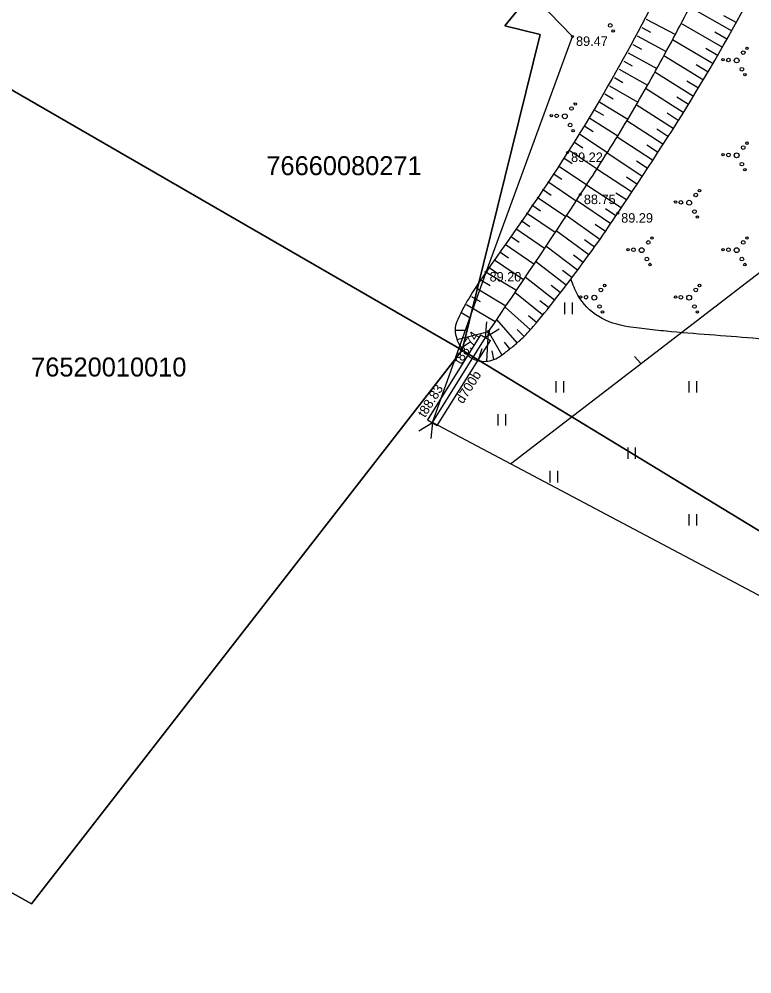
# Model space of a CAD drawing. Extents: x 635228 to 635525, y 248590 to 248800.
# Drawn here: x 635302.2 to 635340.8, y 248626.9 to 248677.2 of the extents above; entities that cross this region are included whole.
import ezdxf

# ---------------------------------------------------------------- set-up
doc = ezdxf.new("R2010")
doc.units = 0
for name, color, linetype in [('HIDT_CAUR_####_####_#', 7, 'Continuous'), ('HIDT_CAUR_####_TKST_#', 7, 'Continuous'), ('HIDT_CAUR_KONT_####_#', 7, 'Continuous'), ('HIDT_ELEM_####_####_#', 7, 'Continuous'), ('RAMI_UZMR_####_####_#', 7, 'Continuous'), ('RELJ_AATZ_####_TKST_#', 7, 'Continuous'), ('RELJ_ELEM_####_####_#', 7, 'Continuous'), ('RELJ_HORZ_RESN_####_#', 7, 'Continuous'), ('RELJ_NOGA_####_####_#', 7, 'Continuous'), ('RELJ_NOGL_####_####_#', 7, 'Continuous'), ('ROBZ_PROJ_####_####_#', 7, 'Continuous'), ('ROBZ_PROJ_####_TKST_#', 7, 'Continuous'), ('ROBZ_UZMR_####_####_#', 7, 'Continuous'), ('ROBZ_UZMR_####_TKST_#', 7, 'Continuous'), ('TERT_ELEM_####_####_#', 7, 'Continuous'), ('TERT_KONT_####_####_#', 7, 'Continuous')]:
    doc.layers.add(name, color=color, linetype=linetype)

msp = doc.modelspace()

# ---------------------------------------------------------------- linework, layer by layer
at = {"layer": 'HIDT_CAUR_####_####_#'}
msp.add_lwpolyline([(635323.971, 248655.917), (635326.77, 248660.394)], dxfattribs=at)
at = {"layer": 'HIDT_CAUR_KONT_####_#'}
for points in [[(635326.511, 248660.545), (635323.712, 248656.068)], [(635326.511, 248660.545), (635327.029, 248660.243)], [(635324.23, 248655.766), (635327.029, 248660.243)], [(635323.712, 248656.068), (635324.23, 248655.766)]]:
    msp.add_lwpolyline(points, dxfattribs=at)
at = {"layer": 'HIDT_ELEM_####_####_#'}
for points in [[(635327.485, 248660.832), (635326.77, 248660.394), (635326.849, 248661.229)], [(635323.256, 248655.479), (635323.971, 248655.917), (635323.892, 248655.082)]]:
    msp.add_lwpolyline(points, dxfattribs=at)
at = {"layer": 'RAMI_UZMR_####_####_#'}
msp.add_lwpolyline([(635379.918, 248627.738), (635364.657, 248634.365), (635359.326, 248636.387), (635355.893, 248639.014), (635323.971, 248655.917), (635326.8, 248663.851), (635331.354, 248676.262), (635327.703, 248680.035), (635326.374, 248681.182), (635325.201, 248682.696), (635327.977, 248685.285), (635332.779, 248692.762), (635338.144, 248706.864), (635340.529, 248716.56), (635346.791, 248738.298), (635351.394, 248755.812), (635352.126, 248761.775)], dxfattribs=at)
at = {"layer": 'RELJ_ELEM_####_####_#'}
for centre in [(635331.354, 248676.262), (635331.093, 248670.147), (635331.766, 248667.928), (635333.734, 248666.95), (635326.8, 248663.851), (635326.936, 248660.713)]:
    msp.add_circle(centre, 0.05, dxfattribs=at)
at = {"layer": 'RELJ_HORZ_RESN_####_#'}
for p, q in [((635328.081, 248653.741), (635341.998, 248664.444)), ((635334.952, 248659.025), (635334.614, 248659.394))]:
    msp.add_line(p, q, dxfattribs=at)
at = {"layer": 'RELJ_NOGA_####_####_#'}
for p, q in [((635339.766, 248676.544), (635337.526, 248677.802)), ((635335.232, 248677.172), (635336.777, 248676.373)), ((635340.009, 248676.981), (635339.33, 248677.356)), ((635335.001, 248676.729), (635335.462, 248676.487)), ((635339.271, 248675.675), (635337.078, 248676.942)), ((635334.768, 248676.286), (635336.294, 248675.475)), ((635339.52, 248676.109), (635338.855, 248676.489)), ((635334.533, 248675.845), (635334.988, 248675.6)), ((635338.764, 248674.813), (635336.625, 248676.089)), ((635339.019, 248675.243), (635338.369, 248675.626)), ((635334.294, 248675.406), (635335.805, 248674.581)), ((635338.247, 248673.957), (635336.163, 248675.233)), ((635334.053, 248674.968), (635334.503, 248674.718)), ((635338.507, 248674.384), (635337.873, 248674.766)), ((635333.561, 248674.098), (635334.007, 248673.841)), ((635333.808, 248674.532), (635335.305, 248673.689)), ((635337.722, 248673.106), (635335.69, 248674.374)), ((635333.31, 248673.665), (635334.793, 248672.795)), ((635337.986, 248673.531), (635337.368, 248673.913)), ((635333.056, 248673.234), (635333.5, 248672.97)), ((635337.189, 248672.26), (635335.208, 248673.519)), ((635332.799, 248672.805), (635334.274, 248671.912)), ((635336.65, 248671.417), (635334.715, 248672.662)), ((635337.456, 248672.683), (635336.854, 248673.062)), ((635332.538, 248672.379), (635332.981, 248672.107)), ((635336.92, 248671.838), (635336.333, 248672.213)), ((635332.274, 248671.954), (635333.745, 248671.032)), ((635336.107, 248670.578), (635334.213, 248671.808)), ((635331.736, 248671.111), (635333.203, 248670.151)), ((635332.007, 248671.532), (635332.448, 248671.25)), ((635336.379, 248670.997), (635335.805, 248671.369)), ((635331.461, 248670.694), (635331.901, 248670.4)), ((635335.561, 248669.74), (635333.7, 248670.957)), ((635331.182, 248670.279), (635332.652, 248669.281)), ((635335.013, 248668.904), (635333.176, 248670.108)), ((635335.835, 248670.159), (635335.272, 248670.526)), ((635330.901, 248669.865), (635331.344, 248669.563)), ((635335.287, 248669.322), (635334.733, 248669.685)), ((635330.619, 248669.452), (635332.105, 248668.439)), ((635334.465, 248668.067), (635332.64, 248669.262)), ((635330.056, 248668.626), (635331.551, 248667.607)), ((635330.338, 248669.039), (635330.785, 248668.734)), ((635334.739, 248668.486), (635334.19, 248668.845)), ((635329.774, 248668.213), (635330.224, 248667.906)), ((635333.917, 248667.231), (635332.093, 248668.421)), ((635329.493, 248667.8), (635330.995, 248666.776)), ((635333.367, 248666.396), (635331.557, 248667.616)), ((635334.191, 248667.649), (635333.644, 248668.007)), ((635329.211, 248667.387), (635329.662, 248667.079)), ((635333.644, 248666.812), (635333.096, 248667.171)), ((635328.647, 248666.56), (635329.101, 248666.251)), ((635328.929, 248666.974), (635330.438, 248665.945)), ((635332.8, 248665.572), (635331.026, 248666.822)), ((635328.366, 248666.147), (635329.882, 248665.114)), ((635333.086, 248665.982), (635332.547, 248666.353)), ((635328.084, 248665.734), (635328.54, 248665.423)), ((635332.218, 248664.759), (635330.489, 248666.02)), ((635332.511, 248665.164), (635331.985, 248665.542)), ((635327.802, 248665.321), (635329.326, 248664.283)), ((635331.622, 248663.956), (635329.95, 248665.215)), ((635327.521, 248664.908), (635327.979, 248664.596)), ((635331.921, 248664.356), (635331.411, 248664.735)), ((635326.957, 248664.082), (635327.418, 248663.768)), ((635327.239, 248664.495), (635328.769, 248663.452)), ((635331.015, 248663.161), (635329.408, 248664.405)), ((635326.8, 248663.851), (635328.4, 248662.9)), ((635330.4, 248662.373), (635328.86, 248663.587)), ((635331.32, 248663.557), (635330.827, 248663.933)), ((635326.544, 248663.421), (635327.017, 248663.14)), ((635330.708, 248662.766), (635330.236, 248663.134)), ((635326.033, 248662.562), (635326.493, 248662.289)), ((635326.289, 248662.992), (635327.843, 248662.067)), ((635329.778, 248661.589), (635328.308, 248662.763)), ((635325.778, 248662.132), (635327.286, 248661.235)), ((635330.09, 248661.981), (635329.638, 248662.339)), ((635325.522, 248661.702), (635325.968, 248661.437)), ((635329.149, 248660.812), (635327.799, 248662.002)), ((635329.466, 248661.199), (635329.035, 248661.544)), ((635325.27, 248661.271), (635325.271, 248661.27)), ((635328.437, 248660.112), (635327.367, 248661.356)), ((635325.17, 248660.786), (635325.719, 248660.792)), ((635325.268, 248660.298), (635326.926, 248660.708)), ((635326.833, 248659.152), (635326.936, 248660.713)), ((635327.637, 248659.483), (635326.936, 248660.713)), ((635328.806, 248660.449), (635328.44, 248660.82)), ((635325.497, 248659.854), (635325.966, 248660.167)), ((635328.049, 248659.796), (635327.77, 248660.154)), ((635326.381, 248659.173), (635326.592, 248659.825)), ((635327.211, 248659.238), (635327.129, 248659.698)), ((635325.818, 248659.473), (635325.819, 248659.473)), ((635326.246, 248659.221), (635326.246, 248659.221))]:
    msp.add_line(p, q, dxfattribs=at)
for points in [[(635375.27, 248754.857), (635369.314, 248744.971), (635367.429, 248741.507), (635365.696, 248737.957), (635363.943, 248734.417), (635363.006, 248732.681), (635362, 248730.984), (635361.355, 248730.103), (635360.628, 248729.283), (635359.885, 248728.474), (635359.193, 248727.625), (635357.58, 248725.368), (635356.018, 248723.079), (635353.089, 248718.349), (635349.569, 248710.638), (635349.163, 248709.221), (635348.864, 248707.772), (635348.539, 248706.335), (635348.053, 248704.954), (635343.12, 248694.162), (635337.407, 248681.667), (635331.093, 248670.147), (635326.8, 248663.851)], [(635326.8, 248663.851), (635325.31, 248661.345), (635325.174, 248660.918), (635325.219, 248660.451), (635325.416, 248659.984), (635325.736, 248659.553), (635326.126, 248659.27), (635326.575, 248659.146), (635327.409, 248659.333), (635327.907, 248659.688), (635328.397, 248660.078), (635328.864, 248660.506), (635329.288, 248660.978), (635331.594, 248663.918), (635332.687, 248665.412), (635333.734, 248666.95), (635337.875, 248673.353), (635341.554, 248680.001), (635347.428, 248693.006), (635353.063, 248706.101), (635354.098, 248708.621), (635355.097, 248711.155), (635356.117, 248713.682), (635356.653, 248714.935), (635357.216, 248716.179), (635358.916, 248719.218), (635360.822, 248722.14), (635362.339, 248724.363), (635363.916, 248726.545), (635365.467, 248728.744), (635366.906, 248731.015), (635368.464, 248733.981), (635369.863, 248737.03), (635371.249, 248740.086), (635372.769, 248743.072), (635378.435, 248753.196)]]:
    msp.add_spline(points, degree=3, dxfattribs=at)
at = {"layer": 'RELJ_NOGL_####_####_#'}
msp.add_spline([(635326.936, 248660.713), (635331.766, 248667.928), (635333.88, 248671.254), (635335.853, 248674.668), (635337.706, 248678.153), (635339.464, 248681.691), (635342.12, 248687.391), (635344.65, 248693.14), (635347.108, 248698.916), (635349.548, 248704.698), (635350.777, 248707.84), (635351.91, 248711.022), (635353.067, 248714.195), (635353.692, 248715.764), (635354.368, 248717.312), (635355.034, 248718.536), (635355.835, 248719.677), (635357.677, 248721.811), (635359.567, 248723.919), (635361.176, 248726.206), (635362.355, 248728.434), (635362.939, 248729.551), (635363.546, 248730.656), (635367.422, 248737.348), (635371.307, 248744.035), (635372.506, 248746.487), (635373.579, 248749.023), (635374.785, 248751.459), (635376.384, 248753.612), (635376.807, 248754.05)], degree=3, dxfattribs=at)
at = {"layer": 'ROBZ_PROJ_####_####_#'}
msp.add_lwpolyline([(635363.321, 248797.676), (635360.888, 248769.918), (635360.483, 248762.615), (635343.343, 248703.12), (635337.46, 248688.66), (635327.79, 248676.828), (635329.653, 248676.366), (635325.542, 248659.74), (635315.4, 248665.602), (635272.581, 248690.35), (635264.056, 248694.511), (635270.042, 248696.015), (635282.096, 248694.845), (635298.597, 248686.068), (635311.236, 248680.45), (635322.498, 248682.379), (635341.086, 248726.313), (635346.481, 248751.583), (635353.471, 248778.803), (635354.805, 248797.676)], dxfattribs=at)
at = {"layer": 'ROBZ_UZMR_####_####_#'}
for points in [[(635325.542, 248659.74), (635329.653, 248676.366), (635327.79, 248676.828), (635337.46, 248688.66), (635343.343, 248703.12), (635360.483, 248762.615), (635458.607, 248711.134), (635465.459, 248707.539), (635439.457, 248681.038), (635424.543, 248670.014), (635420.979, 248667.379), (635407.07, 248653.18), (635400.067, 248641.149), (635395.162, 248617.539), (635389.031, 248621.062), (635375.858, 248629.115)], [(635247.631, 248661.649), (635254.073, 248678.061), (635272.581, 248690.35), (635315.4, 248665.602), (635325.542, 248659.74), (635302.855, 248630.558)]]:
    msp.add_lwpolyline(points, close=True, dxfattribs=at)
msp.add_lwpolyline([(635385.967, 248592.676), (635383.57, 248593.46), (635239.492, 248640.545), (635247.631, 248661.649), (635302.855, 248630.558), (635325.542, 248659.74), (635375.858, 248629.115), (635389.031, 248621.062), (635395.162, 248617.539), (635393.88, 248601.96), (635390.766, 248592.676)], dxfattribs=at)
at = {"layer": 'TERT_ELEM_####_####_#'}
for p, q in [((635330.954, 248661.636), (635330.954, 248662.236)), ((635331.354, 248661.636), (635331.354, 248662.236)), ((635330.5, 248657.5), (635330.5, 248658.1)), ((635330.9, 248657.5), (635330.9, 248658.1)), ((635337.5, 248657.5), (635337.5, 248658.1)), ((635337.9, 248657.5), (635337.9, 248658.1)), ((635327.437, 248655.755), (635327.437, 248656.355)), ((635327.837, 248655.755), (635327.837, 248656.355)), ((635334.279, 248654), (635334.279, 248654.6)), ((635334.679, 248654), (635334.679, 248654.6)), ((635330.183, 248652.766), (635330.183, 248653.366)), ((635330.583, 248652.766), (635330.583, 248653.366)), ((635337.5, 248650.5), (635337.5, 248651.1)), ((635337.9, 248650.5), (635337.9, 248651.1))]:
    msp.add_line(p, q, dxfattribs=at)
for centre, radius in [((635333.34, 248676.842), 0.096), ((635333.497, 248676.553), 0.064), ((635340.544, 248675.639), 0.064), ((635339.282, 248675.034), 0.064), ((635339.566, 248675.021), 0.096), ((635340, 248675), 0.128), ((635340.348, 248675.408), 0.096), ((635340.276, 248674.533), 0.096), ((635340.434, 248674.244), 0.064), ((635331.497, 248672.697), 0.064), ((635330.235, 248672.092), 0.064), ((635330.519, 248672.079), 0.096), ((635330.953, 248672.058), 0.128), ((635331.301, 248672.466), 0.096), ((635331.229, 248671.591), 0.096), ((635331.387, 248671.302), 0.064), ((635340.544, 248670.639), 0.064), ((635339.282, 248670.034), 0.064), ((635339.566, 248670.021), 0.096), ((635340, 248670), 0.128), ((635340.348, 248670.408), 0.096), ((635340.276, 248669.533), 0.096), ((635340.434, 248669.244), 0.064), ((635338.044, 248668.139), 0.064), ((635336.782, 248667.534), 0.064), ((635337.066, 248667.521), 0.096), ((635337.5, 248667.5), 0.128), ((635337.848, 248667.908), 0.096), ((635337.776, 248667.033), 0.096), ((635337.934, 248666.744), 0.064), ((635335.544, 248665.639), 0.064), ((635340.544, 248665.639), 0.064), ((635334.282, 248665.034), 0.064), ((635334.566, 248665.021), 0.096), ((635335, 248665), 0.128), ((635335.348, 248665.408), 0.096), ((635339.282, 248665.034), 0.064), ((635339.566, 248665.021), 0.096), ((635340, 248665), 0.128), ((635340.348, 248665.408), 0.096), ((635335.276, 248664.533), 0.096), ((635340.276, 248664.533), 0.096), ((635335.434, 248664.244), 0.064), ((635340.434, 248664.244), 0.064), ((635333.044, 248663.139), 0.064), ((635338.044, 248663.139), 0.064), ((635331.782, 248662.534), 0.064), ((635332.066, 248662.521), 0.096), ((635332.5, 248662.5), 0.128), ((635332.848, 248662.908), 0.096), ((635336.782, 248662.534), 0.064), ((635337.066, 248662.521), 0.096), ((635337.5, 248662.5), 0.128), ((635337.848, 248662.908), 0.096), ((635332.776, 248662.033), 0.096), ((635337.776, 248662.033), 0.096), ((635332.934, 248661.744), 0.064), ((635337.934, 248661.744), 0.064)]:
    msp.add_circle(centre, radius, dxfattribs=at)
at = {"layer": 'TERT_KONT_####_####_#'}
msp.add_spline([(635353.903, 248658.524), (635343.418, 248660.068), (635342.282, 248660.217), (635341.143, 248660.334), (635338.859, 248660.518), (635336.573, 248660.702), (635335.431, 248660.82), (635334.861, 248660.889), (635334.291, 248660.968), (635332.733, 248661.498), (635331.639, 248662.632), (635331.266, 248663.487)], degree=3, dxfattribs=at)

# ---------------------------------------------------------------- texts
at = {"layer": 'HIDT_CAUR_####_TKST_#'}
for s, p in [('t88.74', (635325.479, 248658.947)), ('d700b', (635325.587, 248656.875)), ('t88.83', (635323.584, 248656.147))]:
    msp.add_text(s, height=0.5, rotation=57.9866, dxfattribs=at).set_placement(p)
at = {"layer": 'RELJ_AATZ_####_TKST_#'}
for s, p in [(' 89.47', (635331.354, 248675.762)), (' 89.22', (635331.093, 248669.647)), (' 88.75', (635331.766, 248667.428)), (' 89.29', (635333.734, 248666.45)), (' 89.20', (635326.8, 248663.351))]:
    msp.add_text(s, height=0.5, dxfattribs=at).set_placement(p)
at = {"layer": 'ROBZ_PROJ_####_TKST_#'}
msp.add_text('76660080271', height=1, dxfattribs=at).set_placement((635315.228, 248668.954))
at = {"layer": 'ROBZ_UZMR_####_TKST_#'}
msp.add_text('76520010010', height=1, dxfattribs=at).set_placement((635302.839, 248658.345))

doc.saveas('drawing.dxf')
